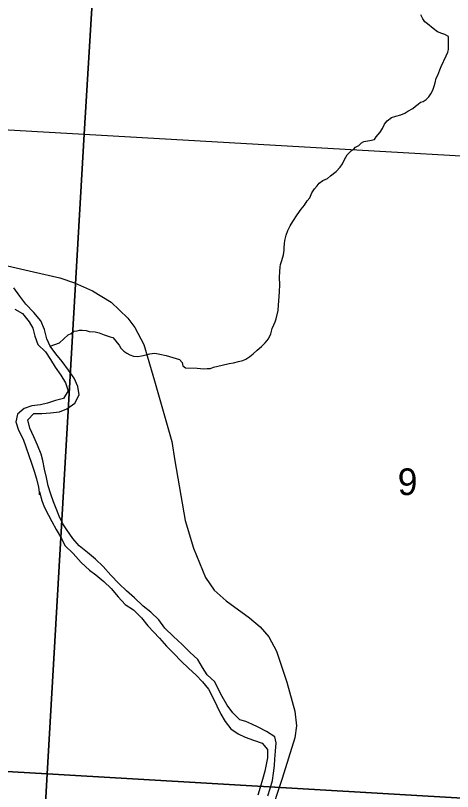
# Model space of a CAD drawing. Extents: x 0 to 34, y 0 to 22.
# Drawn here: x 4.72 to 5.409, y 19.045 to 20.267 of the extents above; entities that cross this region are included whole.
import ezdxf

# ---------------------------------------------------------------- set-up
doc = ezdxf.new("R2010")
doc.units = 0
for name, color, linetype in [('GM_X_Major_River', 7, 'Continuous'), ('GM_X_Minor_River', 7, 'Continuous'), ('GM_X_Section', 7, 'Continuous'), ('GM_X_Section_Text', 7, 'Continuous'), ('GM_X_State_Route', 7, 'Continuous')]:
    doc.layers.add(name, color=color, linetype=linetype)

msp = doc.modelspace()

# ---------------------------------------------------------------- linework, layer by layer
at = {"layer": 'GM_X_Major_River'}
for points in [[(5.1177, 19.0384), (5.1215, 19.0498), (5.1252, 19.0623), (5.1267, 19.0737), (5.1282, 19.0862), (5.1289, 19.0961), (5.1297, 19.1086), (5.1311, 19.1215), (5.1288, 19.131), (5.1159, 19.1396), (5.1027, 19.1464), (5.0928, 19.1513), (5.0833, 19.1551), (5.0739, 19.1581), (5.0625, 19.1691), (5.0538, 19.1812), (5.0458, 19.1944), (5.0408, 19.2046), (5.0343, 19.2175), (5.0222, 19.2288), (5.015, 19.2402), (5.0078, 19.2527), (4.9949, 19.2644), (4.9827, 19.2765), (4.969, 19.2893), (4.9558, 19.3022), (4.9463, 19.3151), (4.9334, 19.3272), (4.9212, 19.337), (4.9079, 19.3498), (4.8954, 19.3608), (4.8829, 19.3725), (4.8707, 19.3857), (4.8582, 19.3994), (4.8465, 19.4107), (4.8336, 19.4213), (4.8207, 19.4319), (4.8104, 19.4436), (4.8009, 19.4568), (4.7948, 19.4667), (4.7891, 19.4784), (4.7853, 19.4882), (4.7803, 19.5011), (4.7758, 19.5132), (4.7719, 19.5265), (4.7693, 19.5394), (4.7662, 19.5526), (4.7635, 19.5659), (4.7605, 19.5761), (4.7551, 19.5905), (4.7494, 19.6034), (4.7426, 19.617), (4.7399, 19.6303), (4.7489, 19.6402), (4.7618, 19.6402), (4.7754, 19.641), (4.7894, 19.6426), (4.8011, 19.6475), (4.8136, 19.6563), (4.8208, 19.6696), (4.8185, 19.6828), (4.8128, 19.6957), (4.804, 19.7082), (4.7938, 19.7218), (4.7839, 19.7339), (4.7748, 19.7464), (4.7694, 19.7577), (4.766, 19.7725), (4.7603, 19.7858), (4.7493, 19.799), (4.7364, 19.8122), (4.7269, 19.8247), (4.7174, 19.838)], [(4.7193, 19.8042), (4.7315, 19.7978), (4.7417, 19.7846)], [(4.7417, 19.7846), (4.7474, 19.7747), (4.7509, 19.7619), (4.7555, 19.749), (4.7676, 19.7373), (4.7756, 19.7252), (4.7828, 19.713), (4.7915, 19.7006), (4.7991, 19.6885), (4.803, 19.676), (4.7958, 19.6638), (4.7833, 19.6604), (4.7708, 19.6565), (4.7595, 19.6538), (4.7462, 19.6523), (4.7338, 19.6481), (4.7236, 19.639), (4.7206, 19.6272), (4.7248, 19.6139), (4.7324, 19.5999), (4.7366, 19.5878), (4.7415, 19.5738), (4.7454, 19.5621), (4.7499, 19.5496), (4.7534, 19.5371), (4.7564, 19.5242), (4.7583, 19.512)], [(4.7583, 19.512), (4.7583, 19.5166), (4.7618, 19.5033), (4.7652, 19.4931), (4.7724, 19.4802), (4.7774, 19.47), (4.7842, 19.4575), (4.7926, 19.4435), (4.7979, 19.4325), (4.8112, 19.4197), (4.8237, 19.4057), (4.837, 19.3936), (4.8469, 19.3864), (4.8594, 19.3755), (4.8712, 19.3645), (4.8822, 19.3513), (4.8932, 19.3392), (4.9061, 19.3309), (4.919, 19.3184), (4.9289, 19.3059), (4.9471, 19.2862), (4.9581, 19.2741), (4.9699, 19.2624), (4.9813, 19.2503), (4.993, 19.239), (5.0048, 19.2284), (5.015, 19.2178), (5.0245, 19.2061), (5.0318, 19.1921), (5.0375, 19.18), (5.0436, 19.1667), (5.0504, 19.155), (5.0595, 19.1436), (5.0709, 19.1357), (5.0823, 19.1308), (5.0952, 19.1259), (5.1088, 19.121), (5.1172, 19.1112), (5.1172, 19.0983), (5.1153, 19.0877), (5.1131, 19.0771), (5.1093, 19.0638), (5.106, 19.0516), (5.1022, 19.0395)]]:
    msp.add_lwpolyline(points, dxfattribs=at)
at = {"layer": 'GM_X_Minor_River'}
for points in [[(5.256, 20.0594), (5.2613, 20.0623), (5.2652, 20.066), (5.269, 20.0682), (5.2785, 20.07), (5.2858, 20.0714), (5.2885, 20.0759), (5.2947, 20.083), (5.2986, 20.089), (5.3017, 20.0958), (5.306, 20.101), (5.3129, 20.1062), (5.3197, 20.108), (5.3273, 20.1102), (5.3335, 20.1127), (5.3384, 20.1161), (5.3461, 20.1205), (5.3507, 20.1238), (5.3545, 20.1272), (5.3584, 20.1302), (5.3626, 20.1312), (5.3672, 20.1346), (5.3714, 20.1387), (5.3749, 20.1436), (5.3777, 20.1492), (5.38, 20.1556), (5.3817, 20.1609), (5.3833, 20.1681), (5.3857, 20.1726), (5.3888, 20.1813), (5.3912, 20.1866), (5.3991, 20.2032), (5.4014, 20.2088), (5.4027, 20.213), (5.4028, 20.2194), (5.4023, 20.2339), (5.397, 20.237), (5.3921, 20.2382), (5.385, 20.241), (5.3782, 20.2464), (5.3697, 20.2538), (5.3655, 20.2569), (5.3622, 20.2615), (5.3589, 20.268)], [(4.7748, 19.7464), (4.7895, 19.7513), (4.8034, 19.7639), (4.808, 19.7661), (4.8122, 19.7695), (4.8175, 19.7705), (4.8213, 19.7712), (4.8251, 19.7715), (4.8316, 19.7707), (4.8365, 19.7694), (4.8459, 19.7685), (4.852, 19.7673), (4.8602, 19.7641), (4.8693, 19.7609), (4.8734, 19.7597), (4.8767, 19.7559), (4.8805, 19.7516), (4.8838, 19.7478), (4.8864, 19.7432), (4.8908, 19.7385), (4.8957, 19.735), (4.9006, 19.7323), (4.9062, 19.7303), (4.913, 19.7298), (4.9187, 19.7308), (4.9263, 19.7326), (4.9317, 19.734), (4.9358, 19.7347), (4.94, 19.735), (4.9476, 19.7338), (4.9578, 19.7317), (4.9736, 19.7269), (4.9789, 19.7249), (4.9829, 19.7203), (4.984, 19.7153), (4.9881, 19.7118), (5.0063, 19.7115), (5.012, 19.7111), (5.0165, 19.7106), (5.0222, 19.7109), (5.0275, 19.7112), (5.0324, 19.713), (5.0461, 19.7162), (5.0568, 19.719), (5.0636, 19.7201), (5.0716, 19.7218), (5.0785, 19.7236), (5.0834, 19.7258), (5.0896, 19.7299), (5.0949, 19.7343), (5.1011, 19.7396), (5.108, 19.7455), (5.1138, 19.7515), (5.1188, 19.7579), (5.1224, 19.7654), (5.1248, 19.7737), (5.1272, 19.7797), (5.1292, 19.7847), (5.1311, 19.7892), (5.134, 19.8024), (5.1349, 19.8111), (5.1354, 19.8168), (5.1359, 19.8248), (5.1364, 19.8316), (5.1366, 19.8434), (5.1364, 19.854), (5.1366, 19.8639), (5.1371, 19.8703), (5.138, 19.8749), (5.14, 19.8809), (5.1428, 19.89), (5.1436, 19.8972), (5.1437, 19.9017), (5.1442, 19.9074), (5.1447, 19.9127), (5.1467, 19.9211), (5.1495, 19.9282), (5.153, 19.9354), (5.1573, 19.9425), (5.1639, 19.9527), (5.1706, 19.962), (5.1756, 19.968), (5.1799, 19.9748), (5.1841, 19.9797), (5.1873, 19.9876), (5.1912, 19.9936), (5.1954, 19.9988), (5.1985, 20.0026), (5.2043, 20.0071), (5.2119, 20.0103), (5.2166, 20.0141), (5.2254, 20.0211), (5.2319, 20.0279), (5.2354, 20.0331), (5.2386, 20.0399), (5.2429, 20.0474), (5.2491, 20.0538), (5.2529, 20.0556), (5.256, 20.0594)]]:
    msp.add_lwpolyline(points, dxfattribs=at)
at = {"layer": 'GM_X_Section'}
for points in [[(3.7913, 20.9), (3.7462, 20.1418), (4.8284, 20.0797), (4.8782, 20.9)], [(4.8782, 20.9), (4.8284, 20.0797), (5.9068, 20.018), (5.9593, 20.9)]]:
    msp.add_lwpolyline(points, dxfattribs=at)
for points in [[(3.7462, 20.1418), (4.8284, 20.0797), (4.7704, 19.0729), (3.6864, 19.1354)], [(4.8284, 20.0797), (5.9068, 20.018), (5.8458, 19.0101), (4.7704, 19.0729)], [(3.6864, 19.1354), (4.7704, 19.0729), (4.7124, 18.0487), (3.6288, 18.1086)], [(5.8458, 19.0101), (5.784, 17.9889), (4.7124, 18.0487), (4.7704, 19.0729)]]:
    msp.add_lwpolyline(points, close=True, dxfattribs=at)
at = {"layer": 'GM_X_State_Route'}
msp.add_lwpolyline([(4.6547, 19.8847), (4.7486, 19.8631), (4.7901, 19.8538), (4.8134, 19.846), (4.8416, 19.8332), (4.8708, 19.8154), (4.8975, 19.7901), (4.9081, 19.7755), (4.9223, 19.749), (4.9395, 19.6917), (4.9665, 19.5962), (4.9714, 19.5657), (4.9874, 19.4716), (5.0008, 19.428), (5.0198, 19.3821), (5.0334, 19.362), (5.052, 19.3453), (5.0889, 19.3182), (5.1056, 19.3045), (5.1197, 19.2887), (5.1317, 19.266), (5.148, 19.2174), (5.1605, 19.1716), (5.163, 19.1484), (5.1603, 19.1295), (5.1406, 19.0654), (5.1202, 19.0037)], dxfattribs=at)

# ---------------------------------------------------------------- texts
at = {"layer": 'GM_X_Section_Text'}
msp.add_text('9', height=0.0419, rotation=0, dxfattribs=at).set_placement((5.3225, 19.5118))

doc.saveas('drawing.dxf')
